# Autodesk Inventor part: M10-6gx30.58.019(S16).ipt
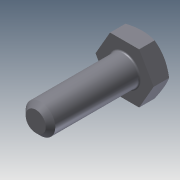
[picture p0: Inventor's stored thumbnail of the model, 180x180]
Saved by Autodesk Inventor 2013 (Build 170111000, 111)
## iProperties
Shininess: 20.0
Length Units: 11269
Angle Units: 11279
Time Units: 11290
Mass Units: 11283
Length Display Precision: 3
Angle Display Precision: 2
Created: 2001-10
Document SubType Name: Modeling
Designer: SaAlex
Material: Steel, Mild
Mass: 30.6674 g
Surface Area: 17.5054 cm^2
Volume: 3.9017 cm^3
Density: 7.86 g/cm^3
Part Number: M10-6gx30.58.019(S16).ipt
Density: 0.0
Volumn: 0.0
Area: 0.0
PropertySet Name: Model Information
Control State: 0
Master: False
Checked Out: False
Checked Out Date: 2008-10-15
Last Check In Date: 2008-10-15
Author: SaAlex
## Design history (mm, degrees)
sketch "Sketch1"
  geometry: L1 (484.39, 469.325)-(474.575, 469.325); L2 (489.297, 460.825)-(484.39, 469.325); L3 (484.39, 452.325)-(489.297, 460.825); L4 (474.575, 452.325)-(484.39, 452.325); L5 (469.667, 460.825)-(474.575, 452.325); L6 (474.575, 469.325)-(469.667, 460.825); C1 r 8.5 at (479.482, 460.825)
  constraints: 12 end point, 6 tangent, 3 parallel, 1 centre point, 1 horizontal, 1 other
  dimensions: "d1" = 120 deg angle of L1 L2; "d3" = 120 deg angle of L5 L6; "d5" = 17 diameter of C1
extrude "ExtrusionBlind1" new body sketch "Sketch1" distance "d6" = 6.4; taper "d7" = 0 deg
sketch "Sketch2"
  geometry: C1 r 7.8 at (479.482, -460.825)
  constraints: 1 centre point
  dimensions: "d12" = 15.6 diameter of C1
extrude "ExtrusionThru1" sketch "Sketch2" stored distance "d13" = 0.13; taper "d14" = 60 deg
sketch "Sketch3"
  geometry: L1 (469.667, 460.825)-(470.167, 461.691); L2 (474.575, 469.325)-(475.575, 469.325); L3 (484.39, 469.325)-(484.89, 468.459); C1 r 5 at (479.482, 460.825); C2 r 8.5 at (479.482, 460.825)
  constraints: 6 end point, 3 tangent, 2 centre point, 1 coincident
  dimensions: "d16" = 10 diameter of C1
extrude "ExtrusionBlind2" join sketch "Sketch3" distance "d17" = 30; taper "d18" = 0 deg
fillet "Fillet1" dims "d19" = 0.5
chamfer "Chamfer1" distance "d20" = 1.6; stored, may be unused: second distance "d21" = 1.6, angle "d22" = 45 deg
body "Solid1"
other parameters: "d0" = 120 deg (derived), "d2" = 120 deg (derived), "d4" = 17 (derived), "d8" = 0, "d9" = 0, "d10" = 0, "d11" = 15.6 (derived), "d23" = 0
